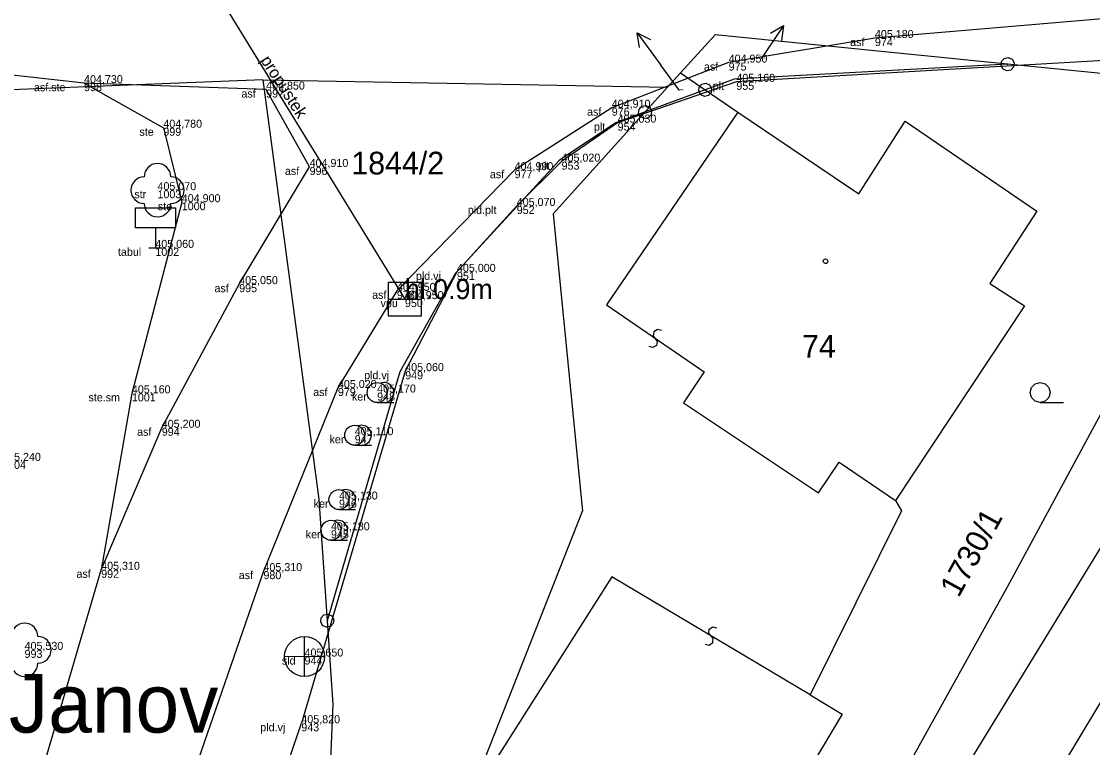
# Model space of a CAD drawing. Extents: x -747792 to -745414, y -1093712 to -1091463.
# Drawn here: x -746996.9 to -746956.76, y -1092186.24 to -1092159.04 of the extents above; entities that cross this region are included whole.
import ezdxf

# ---------------------------------------------------------------- set-up
doc = ezdxf.new("R2010")
doc.units = 0
for name, color, linetype in [('Budovy', 7, 'Continuous'), ('Doplňkové značky', 7, 'Continuous'), ('Doplňující texty', 7, 'Continuous'), ('Hladina', 7, 'Continuous'), ('Koleje_dopravní prvky', 7, 'Continuous'), ('Kultury', 7, 'Continuous'), ('Nezařazené objekty', 7, 'Continuous'), ('Nivelační značky_hrany', 7, 'Continuous'), ('Názvy obcí_ulic', 7, 'Continuous'), ('Ploty_opěrné zdi', 7, 'Continuous'), ('Pracovní_bod JDTM STC_VC - výška', 7, 'Continuous'), ('Pracovní_bod PPBP - výška', 7, 'Continuous'), ('Pracovní_bod PPBP - číslo', 7, 'Continuous'), ('Pracovní_bod ZPBP', 7, 'Continuous'), ('Pracovní_bod ZPBP - číslo', 7, 'Continuous'), ('Rozhraní ploch', 7, 'Continuous'), ('Stromy_porost', 7, 'Continuous'), ('Výškopis', 7, 'Continuous'), ('Čísla popisná_parcelní', 7, 'Continuous')]:
    doc.layers.add(name, color=color, linetype=linetype)

msp = doc.modelspace()

# ---------------------------------------------------------------- linework, layer by layer
at = {"layer": 'Budovy'}
msp.add_lwpolyline([(-746958.73, -1092173.31), (-746958.92, -1092173.26), (-746959.055, -1092173.12), (-746959.105, -1092172.935), (-746959.055, -1092172.75), (-746958.92, -1092172.61), (-746958.73, -1092172.56), (-746958.54, -1092172.61), (-746958.405, -1092172.75), (-746958.355, -1092172.935), (-746958.405, -1092173.12), (-746958.54, -1092173.26), (-746958.73, -1092173.31), (-746957.855, -1092173.31)], dxfattribs=at)
at = {"layer": 'Doplňkové značky'}
for points in [[(-746973.832, -1092159.464), (-746972.94, -1092160.67)], [(-746973.735, -1092160.014), (-746973.832, -1092159.464), (-746973.333, -1092159.717)], [(-746968.342, -1092159.196), (-746969.18, -1092160.44)], [(-746968.828, -1092159.471), (-746968.342, -1092159.196), (-746968.414, -1092159.75)], [(-746972.24, -1092161.62), (-746972.94, -1092160.67)]]:
    msp.add_lwpolyline(points, dxfattribs=at)
at = {"layer": 'Doplňující texty'}
for points in [[(-746960.078, -1092160.423), (-746959.923, -1092160.394), (-746959.782, -1092160.455), (-746959.708, -1092160.589), (-746959.722, -1092160.745), (-746959.822, -1092160.857), (-746959.977, -1092160.886), (-746960.118, -1092160.825), (-746960.192, -1092160.691), (-746960.178, -1092160.535)], [(-746971.408, -1092161.383), (-746971.253, -1092161.354), (-746971.112, -1092161.415), (-746971.038, -1092161.549), (-746971.052, -1092161.705), (-746971.152, -1092161.817), (-746971.307, -1092161.846), (-746971.448, -1092161.785), (-746971.522, -1092161.651), (-746971.508, -1092161.495)], [(-746973.658, -1092162.213), (-746973.503, -1092162.184), (-746973.362, -1092162.245), (-746973.288, -1092162.379), (-746973.302, -1092162.535), (-746973.402, -1092162.647), (-746973.557, -1092162.676), (-746973.698, -1092162.615), (-746973.772, -1092162.481), (-746973.758, -1092162.325)], [(-746985.568, -1092181.273), (-746985.413, -1092181.244), (-746985.272, -1092181.305), (-746985.198, -1092181.439), (-746985.212, -1092181.595), (-746985.312, -1092181.707), (-746985.467, -1092181.736), (-746985.608, -1092181.675), (-746985.682, -1092181.541), (-746985.668, -1092181.385)]]:
    msp.add_lwpolyline(points, close=True, dxfattribs=at)
for points in [[(-746959.967, -1092160.659), (-746959.933, -1092160.621)], [(-746971.297, -1092161.619), (-746971.263, -1092161.581)], [(-746973.547, -1092162.449), (-746973.513, -1092162.411)], [(-746985.457, -1092181.509), (-746985.423, -1092181.471)]]:
    msp.add_lwpolyline(points, dxfattribs=at)
at = {"layer": 'Hladina'}
for p, q in [((-746964.92, -1092159.66), (-746964.92, -1092159.66)), ((-746970.4, -1092160.58), (-746970.4, -1092160.58)), ((-746994.55, -1092161.35), (-746994.55, -1092161.35)), ((-746970.11, -1092161.3), (-746970.11, -1092161.3)), ((-746987.73, -1092161.59), (-746987.73, -1092161.59)), ((-746974.78, -1092162.27), (-746974.78, -1092162.27)), ((-746991.58, -1092163.02), (-746991.58, -1092163.02)), ((-746974.56, -1092162.83), (-746974.56, -1092162.83)), ((-746976.66, -1092164.29), (-746976.66, -1092164.29)), ((-746986.1, -1092164.49), (-746986.1, -1092164.49)), ((-746978.42, -1092164.61), (-746978.42, -1092164.61)), ((-746991.8, -1092165.36), (-746991.8, -1092165.36)), ((-746990.89, -1092165.81), (-746990.89, -1092165.81)), ((-746978.34, -1092165.95), (-746978.34, -1092165.95)), ((-746991.88, -1092167.52), (-746991.88, -1092167.52)), ((-746980.58, -1092168.42), (-746980.58, -1092168.42)), ((-746988.74, -1092168.88), (-746988.74, -1092168.88)), ((-746982.83, -1092169.13), (-746982.83, -1092169.13)), ((-746982.53, -1092169.44), (-746982.53, -1092169.44)), ((-746982.52, -1092172.14), (-746982.52, -1092172.14)), ((-746985.04, -1092172.77), (-746985.04, -1092172.77)), ((-746992.76, -1092172.97), (-746992.76, -1092172.97)), ((-746983.57, -1092172.94), (-746983.57, -1092172.94)), ((-746991.64, -1092174.26), (-746991.64, -1092174.26)), ((-746984.41, -1092174.54), (-746984.41, -1092174.54)), ((-746985, -1092176.95), (-746985, -1092176.95)), ((-746985.3, -1092178.1), (-746985.3, -1092178.1)), ((-746993.91, -1092179.58), (-746993.91, -1092179.58)), ((-746987.83, -1092179.63), (-746987.83, -1092179.63)), ((-746996.78, -1092182.58), (-746996.78, -1092182.58)), ((-746986.29, -1092182.83), (-746986.29, -1092182.83)), ((-746986.41, -1092185.33), (-746986.41, -1092185.33))]:
    msp.add_line(p, q, dxfattribs=at)
at = {"layer": 'Kultury'}
for points in [[(-746970.06, -1092162.44), (-746974.98, -1092169.66)], [(-746974.98, -1092169.66), (-746971.32, -1092172.17)], [(-746972.917, -1092170.62), (-746973.069, -1092170.576), (-746973.206, -1092170.67), (-746973.225, -1092170.821), (-746973.075, -1092171.027), (-746973.105, -1092171.176), (-746973.245, -1092171.256), (-746973.383, -1092171.21)], [(-746971.32, -1092172.17), (-746972.09, -1092173.33)], [(-746972.09, -1092173.33), (-746967.04, -1092176.7)], [(-746967.04, -1092176.7), (-746966.26, -1092175.55)], [(-746966.26, -1092175.55), (-746964.15, -1092176.99)], [(-746974.78, -1092179.85), (-746980.24, -1092188.43)], [(-746967.35, -1092184.27), (-746974.78, -1092179.85)], [(-746971.278, -1092182.369), (-746971.124, -1092182.403), (-746970.993, -1092182.301), (-746970.984, -1092182.149), (-746971.147, -1092181.953), (-746971.127, -1092181.802), (-746970.992, -1092181.713), (-746970.852, -1092181.751)]]:
    msp.add_lwpolyline(points, dxfattribs=at)
at = {"layer": 'Nezařazené objekty'}
for points in [[(-746949.86, -1092160.13), (-746970.11, -1092161.3), (-746974.56, -1092162.83), (-746976.66, -1092164.29), (-746978.34, -1092165.95)], [(-746978.34, -1092165.95), (-746980.58, -1092168.42)], [(-746982.52, -1092172.14), (-746986.41, -1092185.33)]]:
    msp.add_lwpolyline(points, dxfattribs=at)
at = {"layer": 'Nivelační značky_hrany'}
for points in [[(-746898.18, -1092134.6), (-746904.12, -1092139.99), (-746912.01, -1092144.83), (-746920.08, -1092149.17), (-746928.02, -1092152.73), (-746936.45, -1092155.39), (-746944.61, -1092157.47), (-746953.75, -1092158.71), (-746964.92, -1092159.66), (-746970.4, -1092160.58), (-746974.78, -1092162.27), (-746978.42, -1092164.61), (-746982.83, -1092169.13), (-746985.04, -1092172.77), (-746987.83, -1092179.63), (-746991.85, -1092191.24), (-746993.29, -1092198.31), (-746992.77, -1092203.42), (-746990.96, -1092208.81), (-746987.41, -1092214.26), (-746982.51, -1092220.09), (-746977.41, -1092225.71), (-746976.94, -1092226.48)], [(-747011.23, -1092183.09), (-747008.72, -1092181.47), (-747007.03, -1092180.37), (-747005.42, -1092182.85), (-747007.01, -1092183.94), (-747009.54, -1092185.67), (-747002.73, -1092195.47), (-747001.35, -1092196.39), (-746999.16, -1092194.05), (-746996.87, -1092189.68), (-746993.91, -1092179.58), (-746991.64, -1092174.26), (-746988.74, -1092168.88), (-746986.1, -1092164.49), (-746987.73, -1092161.59), (-746994.55, -1092161.35), (-746998.72, -1092160.89), (-747013.92, -1092161.88), (-747014.77, -1092163.04), (-747018.8, -1092163.16), (-747020.75, -1092164.97), (-747020.96, -1092168.13), (-747011.23, -1092183.09)], [(-746994.55, -1092161.35), (-746991.58, -1092163.02), (-746990.89, -1092165.81), (-746992.76, -1092172.97), (-746993.91, -1092179.58)]]:
    msp.add_lwpolyline(points, dxfattribs=at)
at = {"layer": 'Názvy obcí_ulic'}
for p, q in [((-746992.63, -1092166.02), (-746991.13, -1092166.02)), ((-746992.63, -1092166.77), (-746992.63, -1092166.02)), ((-746991.13, -1092166.02), (-746991.13, -1092166.77)), ((-746991.13, -1092166.77), (-746992.63, -1092166.77)), ((-746991.88, -1092166.77), (-746991.88, -1092167.52)), ((-746992.13, -1092167.52), (-746991.63, -1092167.52))]:
    msp.add_line(p, q, dxfattribs=at)
at = {"layer": 'Ploty_opěrné zdi'}
msp.add_lwpolyline([(-746966.77, -1092167.935), (-746966.72, -1092167.945), (-746966.695, -1092167.99), (-746966.685, -1092168.02), (-746966.695, -1092168.065), (-746966.735, -1092168.1), (-746966.77, -1092168.105), (-746966.815, -1092168.09), (-746966.845, -1092168.06), (-746966.855, -1092168.02), (-746966.845, -1092167.975), (-746966.805, -1092167.94)], close=True, dxfattribs=at)
at = {"layer": 'Pracovní_bod JDTM STC_VC - výška'}
for centre in [(-746991.8, -1092165.36), (-746996.78, -1092182.58)]:
    msp.add_circle(centre, 0.0005, dxfattribs=at)
for centre, start, end in [((-746991.8, -1092164.86), 0, 180), ((-746992.3, -1092165.36), 90, 270), ((-746991.3, -1092165.36), 270, 90), ((-746991.8, -1092165.86), 180, 360), ((-746996.78, -1092182.08), 0, 180), ((-746996.28, -1092182.58), 270, 90), ((-746996.78, -1092183.08), 180, 360)]:
    msp.add_arc(centre, 0.5, start, end, dxfattribs=at)
at = {"layer": 'Pracovní_bod PPBP - výška'}
for points in [[(-746980.58, -1092168.42), (-746982.52, -1092172.14)], [(-746987.74, -1092189.24), (-746986.41, -1092185.33)]]:
    msp.add_lwpolyline(points, dxfattribs=at)
at = {"layer": 'Pracovní_bod PPBP - číslo'}
for p, q in [((-746983.57, -1092173.315), (-746982.945, -1092173.315)), ((-746984.41, -1092174.915), (-746983.785, -1092174.915)), ((-746985, -1092177.325), (-746984.375, -1092177.325)), ((-746985.3, -1092178.475), (-746984.675, -1092178.475))]:
    msp.add_line(p, q, dxfattribs=at)
for centre in [(-746983.57, -1092172.94), (-746984.41, -1092174.54), (-746985, -1092176.95), (-746985.3, -1092178.1)]:
    msp.add_circle(centre, 0.375, dxfattribs=at)
for centre in [(-746983.32, -1092172.94), (-746984.16, -1092174.54), (-746984.75, -1092176.95), (-746985.05, -1092178.1)]:
    msp.add_arc(centre, 0.375, 249.4944, 109.0474, dxfattribs=at)
at = {"layer": 'Pracovní_bod ZPBP'}
msp.add_lwpolyline([(-746992.69, -1092152.89), (-746982.53, -1092169.44)], dxfattribs=at)
at = {"layer": 'Stromy_porost'}
for points in [[(-746970.91, -1092159.54), (-746972.2, -1092160.96)], [(-746959.95, -1092160.64), (-746970.91, -1092159.54)], [(-746945.49, -1092160), (-746948.23, -1092165.29), (-746962.05, -1092187.86), (-746971.93, -1092204.37)], [(-746959.95, -1092160.64), (-746970.19, -1092161.2)], [(-746949.91, -1092161.64), (-746959.95, -1092160.64)], [(-746972.2, -1092160.96), (-746972.69, -1092161.5)], [(-746972.2, -1092160.96), (-746971.28, -1092161.6)], [(-746987.85, -1092161.22), (-747021.82, -1092162.57)], [(-746987.85, -1092161.22), (-746985.75, -1092176.94)], [(-746987.85, -1092161.22), (-746972.69, -1092161.5)], [(-746973.53, -1092162.43), (-746972.69, -1092161.5)], [(-746970.19, -1092161.2), (-746971.28, -1092161.6)], [(-746971.28, -1092161.6), (-746973.53, -1092162.43)], [(-746971.28, -1092161.6), (-746970.06, -1092162.44)], [(-746959.95, -1092180.22), (-746949.91, -1092161.64)], [(-746976.98, -1092166.24), (-746973.53, -1092162.43)], [(-746973.53, -1092162.43), (-746974.63, -1092162.83)], [(-746970.06, -1092162.44), (-746965.52, -1092165.5)], [(-746974.63, -1092162.83), (-746976.74, -1092164.24)], [(-746965.52, -1092165.5), (-746963.79, -1092162.77)], [(-746963.79, -1092162.77), (-746958.85, -1092166.14)], [(-746976.74, -1092164.24), (-746980.64, -1092168.47)], [(-746976.98, -1092166.24), (-746975.87, -1092177.38)], [(-746958.85, -1092166.14), (-746960.61, -1092168.85)], [(-746980.64, -1092168.47), (-746982.72, -1092172.16)], [(-746960.61, -1092168.85), (-746959.32, -1092169.69)], [(-746959.32, -1092169.69), (-746964.15, -1092176.99)], [(-746982.72, -1092172.16), (-746985.44, -1092181.49)], [(-746985.75, -1092176.94), (-746985.44, -1092181.49)], [(-746964.15, -1092176.99), (-746963.93, -1092177.37)], [(-746980.24, -1092188.43), (-746975.87, -1092177.38)], [(-746963.93, -1092177.37), (-746967.35, -1092184.27)], [(-746963.7, -1092186.96), (-746959.95, -1092180.22)], [(-746960.47, -1092191.19), (-746954.11, -1092180.64)], [(-746985.44, -1092181.49), (-746985.23, -1092184.63)], [(-746967.35, -1092184.27), (-746966.15, -1092184.99)], [(-746985.23, -1092184.63), (-746985.44, -1092189.59)], [(-746966.15, -1092184.99), (-746975.42, -1092200.54)]]:
    msp.add_lwpolyline(points, dxfattribs=at)
at = {"layer": 'Čísla popisná_parcelní'}
for p, q in [((-746981.904, -1092168.813), (-746983.155, -1092168.813)), ((-746983.155, -1092168.813), (-746983.155, -1092170.067)), ((-746981.904, -1092170.067), (-746981.904, -1092168.813)), ((-746983.155, -1092169.44), (-746981.905, -1092169.44)), ((-746983.155, -1092170.067), (-746981.904, -1092170.067)), ((-746986.291, -1092183.578), (-746986.29, -1092182.083)), ((-746985.538, -1092182.836), (-746987.038, -1092182.831))]:
    msp.add_line(p, q, dxfattribs=at)
msp.add_circle((-746986.29, -1092182.83), 0.75, dxfattribs=at)

# ---------------------------------------------------------------- texts
at = {"layer": 'Doplňkové značky'}
msp.add_text('Janov', height=2.2, dxfattribs=at).set_placement((-746997.367, -1092185.68))
at = {"layer": 'Koleje_dopravní prvky'}
for s, height, p in [('1730/2', 0.05, (-746969.18, -1092160.44)), ('1905', 0.05, (-746972.24, -1092161.62)), ('1844/2', 0.85, (-746984.537, -1092164.77)), ('74', 0.85, (-746967.652, -1092171.63))]:
    msp.add_text(s, height=height, dxfattribs=at).set_placement(p)
msp.add_text('1730/1', height=0.85, rotation=61.1919, dxfattribs=at).set_placement((-746961.783, -1092180.653))
at = {"layer": 'Pracovní_bod ZPBP - číslo'}
msp.add_text('propustek', height=0.45, rotation=302.7888, dxfattribs=at).set_placement((-746987.957, -1092160.492))
msp.add_text('hl.0.9m', height=0.75, dxfattribs=at).set_placement((-746982.53, -1092169.44))
at = {"layer": 'Rozhraní ploch'}
for s, p in [(' asf', (-746965.957, -1092159.96)), ('974', (-746964.92, -1092159.96)), (' asf', (-746971.437, -1092160.88)), ('975', (-746970.4, -1092160.88)), (' asf.ste', (-746996.541, -1092161.65)), ('998', (-746994.55, -1092161.65)), (' plt', (-746971.109, -1092161.6)), ('955', (-746970.11, -1092161.6)), (' asf', (-746988.767, -1092161.89)), ('997', (-746987.73, -1092161.89)), (' asf', (-746975.817, -1092162.57)), ('976', (-746974.78, -1092162.57)), (' ste', (-746992.589, -1092163.32)), ('999', (-746991.58, -1092163.32)), (' plt', (-746975.559, -1092163.13)), ('954', (-746974.56, -1092163.13)), (' plt', (-746977.659, -1092164.59)), ('953', (-746976.66, -1092164.59)), (' asf', (-746987.137, -1092164.79)), ('996', (-746986.1, -1092164.79)), (' asf', (-746979.457, -1092164.91)), ('977', (-746978.42, -1092164.91)), (' str', (-746992.778, -1092165.66)), ('1003', (-746991.8, -1092165.66)), (' ste', (-746991.899, -1092166.11)), ('1000', (-746990.89, -1092166.11)), (' pld.plt', (-746980.284, -1092166.25)), ('952', (-746978.34, -1092166.25)), (' tabul', (-746993.392, -1092167.82)), ('1002', (-746991.88, -1092167.82)), (' pld.vj', (-746982.229, -1092168.72)), ('951', (-746980.58, -1092168.72)), (' asf', (-746989.777, -1092169.18)), ('995', (-746988.74, -1092169.18)), (' asf', (-746983.867, -1092169.43)), ('978', (-746982.83, -1092169.43)), (' vpu', (-746983.553, -1092169.74)), ('950', (-746982.53, -1092169.74)), (' pld.vj', (-746984.169, -1092172.44)), ('949', (-746982.52, -1092172.44)), (' asf', (-746986.077, -1092173.07)), ('979', (-746985.04, -1092173.07)), (' ste.sm', (-746994.498, -1092173.27)), ('1001', (-746992.76, -1092173.27)), (' ker', (-746984.626, -1092173.24)), ('948', (-746983.57, -1092173.24)), (' asf', (-746992.677, -1092174.56)), ('994', (-746991.64, -1092174.56)), (' ker', (-746985.466, -1092174.84)), ('947', (-746984.41, -1092174.84)), ('1004', (-746997.62, -1092175.8)), (' ker', (-746986.056, -1092177.25)), ('946', (-746985, -1092177.25)), (' ker', (-746986.356, -1092178.4)), ('945', (-746985.3, -1092178.4)), (' asf', (-746994.947, -1092179.88)), ('992', (-746993.91, -1092179.88)), (' asf', (-746988.867, -1092179.93)), ('980', (-746987.83, -1092179.93)), ('993', (-746996.78, -1092182.88)), (' sld', (-746987.251, -1092183.13)), ('944', (-746986.29, -1092183.13)), (' pld.vj', (-746988.059, -1092185.63)), ('943', (-746986.41, -1092185.63))]:
    msp.add_text(s, height=0.3, dxfattribs=at).set_placement(p)
at = {"layer": 'Výškopis'}
for s, p in [('405,180', (-746964.92, -1092159.66)), ('404,950', (-746970.4, -1092160.58)), ('404,730', (-746994.55, -1092161.35)), ('405,160', (-746970.11, -1092161.3)), ('404,850', (-746987.73, -1092161.59)), ('404,910', (-746974.78, -1092162.27)), ('404,780', (-746991.58, -1092163.02)), ('405,030', (-746974.56, -1092162.83)), ('404,910', (-746986.1, -1092164.49)), ('404,990', (-746978.42, -1092164.61)), ('405,020', (-746976.66, -1092164.29)), ('405,070', (-746991.8, -1092165.36)), ('404,900', (-746990.89, -1092165.81)), ('405,070', (-746978.34, -1092165.95)), ('405,060', (-746991.88, -1092167.52)), ('405,000', (-746980.58, -1092168.42)), ('405,050', (-746988.74, -1092168.88)), ('404,950', (-746982.83, -1092169.13)), ('404,950', (-746982.53, -1092169.44)), ('405,060', (-746982.52, -1092172.14)), ('405,160', (-746992.76, -1092172.97)), ('405,020', (-746985.04, -1092172.77)), ('405,170', (-746983.57, -1092172.94)), ('405,200', (-746991.64, -1092174.26)), ('405,110', (-746984.41, -1092174.54)), ('405,240', (-746997.62, -1092175.5)), ('405,130', (-746985, -1092176.95)), ('405,180', (-746985.3, -1092178.1)), ('405,310', (-746993.91, -1092179.58)), ('405,310', (-746987.83, -1092179.63)), ('405,530', (-746996.78, -1092182.58)), ('405,650', (-746986.29, -1092182.83)), ('405,820', (-746986.41, -1092185.33))]:
    msp.add_text(s, height=0.3, dxfattribs=at).set_placement(p)

doc.saveas('drawing.dxf')
